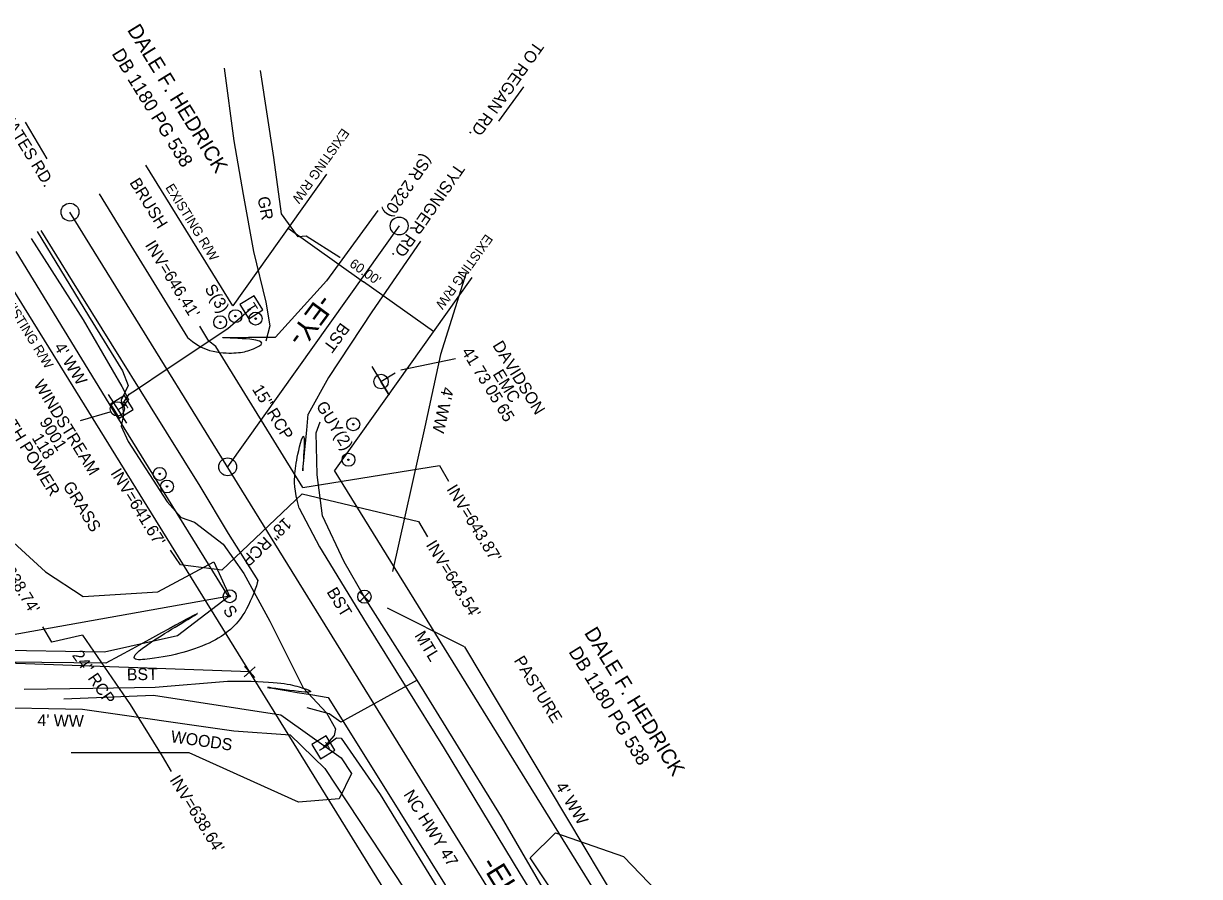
# Model space of a CAD drawing. Extents: x 1666477 to 1667385, y 697735 to 699095.
# Drawn here: x 1666778 to 1667173.7, y 698609.2 to 698896.5 of the extents above; entities that cross this region are included whole.
import ezdxf

# ---------------------------------------------------------------- set-up
doc = ezdxf.new("R2010")
doc.units = 0
for name, color, linetype in [('Exist Horizontal Alignment', 7, 'Continuous'), ('Exist Horizontal Alignment Direction Label', 7, 'Continuous'), ('Exist Horizontal Alignment Point', 7, 'Continuous'), ('Exist Other Culture Anchor (Guy Wire) CELL', 7, 'Continuous'), ('Exist Other Culture Fence Line', 7, 'Continuous'), ('Exist Other Culture Fence Line Text', 7, 'Continuous'), ('Exist Other Culture Gate', 7, 'Continuous'), ('Exist Other Culture Gate Text', 7, 'Continuous'), ('Exist Other Culture Sign CELL', 7, 'Continuous'), ('Exist Other Culture Sign Text', 7, 'Continuous'), ('Exist Property Corner CELL', 7, 'Continuous'), ('Exist Property Deed Book Text', 7, 'Continuous'), ('Exist Property Line', 7, 'Continuous'), ('Exist Property Owner Text', 7, 'Continuous'), ('Exist Right of Way Line', 7, 'Continuous'), ('Exist Right of Way Line Text', 7, 'Continuous'), ('Exist Right of Way Width CELL', 7, 'Continuous'), ('Exist Roads EOP', 7, 'Continuous'), ('Exist Roads EOP Leader', 7, 'Continuous'), ('Exist Roads EOP Text', 7, 'Continuous'), ('Exist Roads Soil', 7, 'Continuous'), ('Exist Roads Soil Text', 7, 'Continuous'), ('Exist Structure Minor Pipes RCP 15 Inch', 7, 'Continuous'), ('Exist Structure Minor Pipes RCP 15 Inch Invert', 7, 'Continuous'), ('Exist Structure Minor Pipes RCP 15 Inch Leader', 7, 'Continuous'), ('Exist Structure Minor Pipes RCP 15 Inch Text', 7, 'Continuous'), ('Exist Structure Minor Pipes RCP 18 Inch', 7, 'Continuous'), ('Exist Structure Minor Pipes RCP 18 Inch Invert', 7, 'Continuous'), ('Exist Structure Minor Pipes RCP 18 Inch Leader', 7, 'Continuous'), ('Exist Structure Minor Pipes RCP 18 Inch Text', 7, 'Continuous'), ('Exist Structure Minor Pipes RCP 24 Inch', 7, 'Continuous'), ('Exist Structure Minor Pipes RCP 24 Inch Invert', 7, 'Continuous'), ('Exist Structure Minor Pipes RCP 24 Inch Leader', 7, 'Continuous'), ('Exist Structure Minor Pipes RCP 24 Inch Text', 7, 'Continuous'), ('Exist Utilities Power Joint Use Telephone CELL', 7, 'Continuous'), ('Exist Utilities Power Joint Use Telephone Leader', 7, 'Continuous'), ('Exist Utilities Power Joint Use Telephone Text', 7, 'Continuous'), ('Exist Utilities Telephone Pedestal CELL', 7, 'Continuous'), ('Exist Utilities Telephone Pole CELL', 7, 'Continuous'), ('Exist Utilities Telephone Pole Leader', 7, 'Continuous'), ('Exist Utilities Telephone Pole Text', 7, 'Continuous'), ('Exist Utilities Telephone UG Cable SUE LOS C', 7, 'Continuous'), ('Exist Utilities Water UG Line SUE LOS C', 7, 'Continuous'), ('Exist Utilities Water Valve CELL', 7, 'Continuous'), ('Exist Vegetation Woods Line', 7, 'Continuous'), ('Exist Vegetation Woods Line Text', 7, 'Continuous')]:
    doc.layers.add(name, color=color, linetype=linetype)

msp = doc.modelspace()

# ---------------------------------------------------------------- linework, layer by layer
at = {"layer": 'Exist Horizontal Alignment'}
for p, q in [((1667148.23, 698259.58), (1666793.59, 698833.01)), ((1666904.4, 698828.35), (1666846.65, 698747.21))]:
    msp.add_line(p, q, dxfattribs=at)
at = {"layer": 'Exist Horizontal Alignment Point'}
for centre in [(1666793.59, 698833.01), (1666904.4, 698828.35), (1666846.66, 698747.21)]:
    msp.add_circle(centre, 3, dxfattribs=at)
at = {"layer": 'Exist Other Culture Anchor (Guy Wire) CELL'}
for centre, radius in [((1666888.93, 698761.56), 2.18), ((1666888.93, 698761.56), 0.24), ((1666887.33, 698749.59), 2.18), ((1666823.79, 698744.85), 2.18), ((1666887.33, 698749.59), 0.24), ((1666823.79, 698744.85), 0.24), ((1666826.25, 698740.6), 2.18), ((1666826.25, 698740.6), 0.24)]:
    msp.add_circle(centre, radius, dxfattribs=at)
at = {"layer": 'Exist Other Culture Fence Line'}
msp.add_line((1666926.39, 698686.64), (1666991.9, 698577.03), dxfattribs=at)
for points in [[(1666765.7, 698685.55), (1666805.24, 698684.86), (1666829.81, 698690.37), (1666846.99, 698703.56), (1666807.98, 698766.53), (1666775.47, 698819.74)], [(1666926.99, 698812.53), (1666918.33, 698785.01), (1666912.99, 698760.65), (1666902.09, 698711.93)], [(1666763.48, 698666.33), (1666797.8, 698665.64), (1666797.79, 698665.65), (1666848.77, 698658.33), (1666867.75, 698656.95), (1666879.42, 698645.59), (1666913.77, 698593.47), (1666938.8, 698553.46), (1666968.81, 698505.62), (1666992.27, 698464), (1667007.43, 698434.44)]]:
    msp.add_lwpolyline(points, dxfattribs=at)
at = {"layer": 'Exist Other Culture Gate'}
msp.add_line((1666926.39, 698686.64), (1666900.51, 698699.65), dxfattribs=at)
at = {"layer": 'Exist Other Culture Sign CELL'}
for centre, radius in [((1666849.29, 698797.97), 2.18), ((1666849.29, 698797.97), 0.24), ((1666856.08, 698797.14), 2.18), ((1666844.15, 698795.93), 2.18), ((1666844.15, 698795.93), 0.24), ((1666856.08, 698797.14), 0.24), ((1666847.36, 698703.64), 2.18), ((1666847.36, 698703.64), 0.24)]:
    msp.add_circle(centre, radius, dxfattribs=at)
at = {"layer": 'Exist Property Corner CELL'}
msp.add_line((1666854.1, 698678.14), (1666854.1, 698678.14), dxfattribs=at)
msp.add_lwpolyline([(1666855.93, 698679.84), (1666852.27, 698676.44), (1666854.1, 698678.14), (1666855.8, 698676.31), (1666852.39, 698679.97)], dxfattribs=at)
at = {"layer": 'Exist Property Line'}
msp.add_line((1666854.1, 698678.14), (1666599.41, 698687.39), dxfattribs=at)
at = {"layer": 'Exist Right of Way Line'}
for p, q in [((1666848.41, 698801.41), (1666819.1, 698848.79)), ((1666879.96, 698845.74), (1666848.41, 698801.41)), ((1667122.72, 698243.8), (1666768.07, 698817.23)), ((1666928.84, 698810.95), (1666882.65, 698746.04)), ((1667173.75, 698275.36), (1666882.65, 698746.04))]:
    msp.add_line(p, q, dxfattribs=at)
at = {"layer": 'Exist Right of Way Width CELL'}
for p in [(1666867.03, 698827.57), (1666915.91, 698792.78)]:
    msp.add_line(p, (1666892.41, 698809.51), dxfattribs=at)
at = {"layer": 'Exist Roads EOP'}
for points in [[(1666803.4, 698839.18), (1666814.05, 698821.74), (1666833.19, 698790.74)], [(1666897.2, 698833.52), (1666879.9, 698809.91), (1666862.77, 698790.89)], [(1666783.78, 698826.85), (1666794.34, 698809.8), (1666820.54, 698767.52), (1666837.34, 698740.76), (1666846.83, 698724.76), (1666856.77, 698708.99)], [(1666911.61, 698823.18), (1666895.16, 698799.38), (1666880.58, 698777.36), (1666873.81, 698765)], [(1666870.75, 698733.33), (1666877.61, 698720.31), (1666893.3, 698694.61), (1666919.49, 698652.35), (1666945, 698610.31), (1666971.56, 698567.04), (1666997.43, 698525.34), (1667023.64, 698482.78), (1667049.97, 698441.03), (1667054.17, 698434.34), (1667055.97, 698432.32), (1667056, 698431.95), (1667056.6, 698430.99)], [(1666805.65, 698681.07), (1666773.35, 698681.38)], [(1666778.16, 698672.37), (1666801.29, 698672.66), (1666822.31, 698673.06), (1666846.6, 698675.09)], [(1666880.47, 698669.55), (1666899.28, 698639.61), (1666924.98, 698598.12), (1666951.86, 698555.5), (1666977.68, 698512.7), (1667003.52, 698470.73), (1667029.64, 698428.31), (1667043.53, 698406.89), (1667043.73, 698406.63)]]:
    msp.add_lwpolyline(points, dxfattribs=at)
for points in [[(1666833.19, 698790.74), (1666837.58, 698786.86), (1666844.75, 698785.32), (1666851.46, 698785.64), (1666855.49, 698786.82), (1666862.77, 698790.89), (1666833.19, 698790.74), (1666862.77, 698790.89)], [(1666870.75, 698733.33), (1666869, 698739.55), (1666869.22, 698745.28), (1666870.12, 698751.47), (1666873.81, 698765), (1666870.75, 698733.33), (1666873.81, 698765)], [(1666856.77, 698708.99), (1666856.57, 698707.18), (1666852.74, 698697.92), (1666848.65, 698693.07), (1666842.23, 698688.26), (1666831.44, 698684.3), (1666821.38, 698682.47), (1666805.65, 698681.07), (1666856.77, 698708.99), (1666805.65, 698681.07)], [(1666846.6, 698675.09), (1666862.82, 698675.06), (1666871.25, 698673.31), (1666880.47, 698669.55), (1666846.6, 698675.09), (1666880.47, 698669.55)]]:
    msp.add_open_spline(points, degree=3, dxfattribs=at)
at = {"layer": 'Exist Roads EOP Leader'}
for points in [[(1666946.28, 698875.17), (1666937.78, 698863.66)], [(1666778.51, 698863.25), (1666785.83, 698850.96)]]:
    msp.add_lwpolyline(points, dxfattribs=at)
at = {"layer": 'Exist Roads Soil'}
for points in [[(1666845.46, 698881.53), (1666848.73, 698857.02), (1666851.83, 698838.9), (1666855.41, 698819.75), (1666859.46, 698802.71), (1666860.87, 698794.69), (1666859.47, 698789.51)], [(1666884.51, 698817.76), (1666884.47, 698817.75), (1666873.11, 698824.92), (1666870.45, 698824.72), (1666864.78, 698832.43), (1666862.19, 698851.45), (1666857.77, 698880.69)]]:
    msp.add_lwpolyline(points, dxfattribs=at)
at = {"layer": 'Exist Structure Minor Pipes RCP 15 Inch'}
msp.add_line((1666872.01, 698740.31), (1666842.63, 698787.74), dxfattribs=at)
at = {"layer": 'Exist Structure Minor Pipes RCP 15 Inch Leader'}
for points in [[(1666842.63, 698787.74), (1666840.32, 698789.5), (1666837.26, 698794.65)], [(1666872.01, 698740.31), (1666917.95, 698747.65), (1666920.94, 698742.45)]]:
    msp.add_lwpolyline(points, dxfattribs=at)
at = {"layer": 'Exist Structure Minor Pipes RCP 18 Inch'}
msp.add_line((1666871.77, 698738.09), (1666844.76, 698712.45), dxfattribs=at)
at = {"layer": 'Exist Structure Minor Pipes RCP 18 Inch Leader'}
for points in [[(1666871.77, 698738.09), (1666910.88, 698728.85), (1666913.94, 698723.69)], [(1666844.76, 698712.45), (1666830.83, 698714.21), (1666827.43, 698719.15)]]:
    msp.add_lwpolyline(points, dxfattribs=at)
at = {"layer": 'Exist Structure Minor Pipes RCP 24 Inch'}
msp.add_line((1666797.79, 698690.52), (1666813.8, 698667.16), dxfattribs=at)
at = {"layer": 'Exist Structure Minor Pipes RCP 24 Inch Leader'}
for points in [[(1666797.79, 698690.52), (1666787.5, 698688.2), (1666784.44, 698693.36)], [(1666813.8, 698667.16), (1666824.59, 698649.72), (1666827.68, 698644.58)]]:
    msp.add_lwpolyline(points, dxfattribs=at)
at = {"layer": 'Exist Utilities Power Joint Use Telephone CELL'}
msp.add_line((1666898.29, 698775.95), (1666898.29, 698775.95), dxfattribs=at)
msp.add_lwpolyline([(1666895.2, 698781.03), (1666901.06, 698771.32), (1666898.27, 698775.94), (1666903.09, 698778.87)], dxfattribs=at)
msp.add_circle((1666898.29, 698775.95), 2.45, dxfattribs=at)
at = {"layer": 'Exist Utilities Power Joint Use Telephone Leader'}
msp.add_line((1666904.91, 698779.87), (1666923.37, 698783.67), dxfattribs=at)
at = {"layer": 'Exist Utilities Telephone Pedestal CELL'}
for p, q in [((1666854.63, 698801.04), (1666854.63, 698801.04)), ((1666811.02, 698767.53), (1666811.02, 698767.53)), ((1666878.86, 698652.84), (1666878.86, 698652.84))]:
    msp.add_line(p, q, dxfattribs=at)
for points in [[(1666850.79, 698801.87), (1666853.74, 698797.12), (1666858.5, 698800.07), (1666855.55, 698804.82), (1666850.79, 698801.87)], [(1666807.18, 698768.35), (1666810.13, 698763.6), (1666814.88, 698766.55), (1666811.93, 698771.3), (1666807.18, 698768.35)], [(1666875.03, 698653.68), (1666877.96, 698648.91), (1666882.73, 698651.85), (1666879.79, 698656.61), (1666875.03, 698653.68)]]:
    msp.add_lwpolyline(points, dxfattribs=at)
at = {"layer": 'Exist Utilities Telephone Pole CELL'}
for p, q in [((1666806.5, 698771.53), (1666812.6, 698761.98)), ((1666809.55, 698766.75), (1666809.55, 698766.75))]:
    msp.add_line(p, q, dxfattribs=at)
msp.add_circle((1666809.55, 698766.75), 2.41, dxfattribs=at)
at = {"layer": 'Exist Utilities Telephone Pole Leader'}
msp.add_line((1666807.05, 698765.63), (1666797.06, 698762.66), dxfattribs=at)
at = {"layer": 'Exist Utilities Telephone UG Cable SUE LOS C'}
for points in [[(1666782.53, 698826.44), (1666799.81, 698798.03), (1666811.32, 698779.59), (1666813.23, 698774.6), (1666810.77, 698769.62), (1666811.38, 698766.84), (1666811.63, 698764.7), (1666810.81, 698760.95), (1666813.15, 698755.81), (1666826.32, 698735.48), (1666831.02, 698730.12), (1666835.56, 698728.55), (1666845.16, 698721.16), (1666852.11, 698711.31), (1666860.89, 698695.27), (1666872.06, 698672.78), (1666879.9, 698664.39), (1666882.94, 698659), (1666882.55, 698656.73), (1666880.09, 698653.9), (1666881.02, 698654.39), (1666878.94, 698652.93)], [(1666780.57, 698824.13), (1666798.05, 698796.74), (1666811.03, 698774.3), (1666813.24, 698769.92), (1666811.46, 698767.78)], [(1666811.01, 698768.02), (1666813.55, 698771.71), (1666815.99, 698773.31), (1666826.01, 698779.96), (1666846.68, 698793.81), (1666854.51, 698800.55)], [(1666879.11, 698652.82), (1666883.33, 698655.98), (1666884.9, 698655.82), (1666898.04, 698636.86), (1666923.51, 698595.3), (1666949.94, 698553.7), (1666963.27, 698526.7), (1666963.8, 698522.77), (1666984.35, 698489.78), (1666990.94, 698476.64), (1667004.92, 698449.71), (1667010.1, 698440.1), (1667007, 698437.59)]]:
    msp.add_lwpolyline(points, dxfattribs=at)
at = {"layer": 'Exist Utilities Water UG Line SUE LOS C'}
for points in [[(1666876.74, 698744.58), (1666876.47, 698758.66), (1666877.77, 698762.39)], [(1666910.42, 698675.41), (1666892.7, 698703.36), (1666885.87, 698715.18), (1666878.61, 698730.69), (1666876.74, 698744.58)], [(1667059.41, 698444.14), (1667051.92, 698448.86), (1667045.14, 698458.4), (1667032.4, 698476.75), (1667019.73, 698495.63), (1666997.89, 698531.42), (1666986.24, 698552.11), (1666969.96, 698576.95), (1666955.37, 698600.92), (1666938.85, 698629.31), (1666923.47, 698654.27), (1666910.42, 698675.41), (1666884.79, 698661.27), (1666880.83, 698664.06), (1666873.43, 698666)]]:
    msp.add_lwpolyline(points, dxfattribs=at)
at = {"layer": 'Exist Utilities Water Valve CELL'}
msp.add_lwpolyline([(1666894.27, 698705.06), (1666891.11, 698701.91), (1666892.69, 698703.49), (1666894.27, 698701.91), (1666891.11, 698705.06)], dxfattribs=at)
msp.add_circle((1666892.69, 698703.49), 2.23, dxfattribs=at)
at = {"layer": 'Exist Vegetation Woods Line'}
for points in [[(1666767.69, 698727.95), (1666785.4, 698711.88), (1666798.08, 698703.59), (1666823.22, 698705.08), (1666842, 698715.28), (1666847.33, 698703.65), (1666770.13, 698689.87)], [(1666791.52, 698669.07), (1666821.73, 698670.35), (1666864.58, 698663.64), (1666884.87, 698649.22), (1666888.32, 698643.89)], [(1666888.32, 698643.89), (1666884.15, 698635.36), (1666870.48, 698634.32), (1666833.7, 698650.92), (1666794.02, 698650.95)], [(1666997.11, 698574.49), (1666965.25, 698590.45), (1666948.43, 698615.52), (1666956.99, 698623.99), (1666979.86, 698615.98), (1667005.31, 698589.51), (1667026.65, 698580.74), (1667046.61, 698594.4)]]:
    msp.add_lwpolyline(points, dxfattribs=at)

# ---------------------------------------------------------------- texts
at = {"layer": 'Exist Horizontal Alignment Direction Label'}
for s, rotation, p in [('-EY-', 233.487, (1666877.68, 698805.9)), ('-EL-', 301.6959, (1666931.68, 698613.44))]:
    msp.add_text(s, height=7, rotation=rotation, dxfattribs=at).set_placement(p)
at = {"layer": 'Exist Other Culture Fence Line Text'}
for rotation, p in [(301.4175, (1666788.08, 698787.59)), (257.2589, (1666918.93, 698774.38)), (358.8481, (1666782.62, 698659.94)), (300.8653, (1666956.82, 698639.62))]:
    msp.add_text("4' WW", height=4, rotation=rotation, dxfattribs=at).set_placement(p)
at = {"layer": 'Exist Other Culture Gate Text'}
msp.add_text('MTL', height=4, rotation=301.3048, dxfattribs=at).set_placement((1666909.42, 698690.43))
at = {"layer": 'Exist Other Culture Sign Text'}
for s, rotation, p in [('S(3)', 301.6959, (1666838.77, 698807.22)), ('GUY(2)', 301.6959, (1666876.25, 698767.8)), ('S', 305.0453, (1666844.92, 698698.86))]:
    msp.add_text(s, height=4, rotation=rotation, dxfattribs=at).set_placement(p)
at = {"layer": 'Exist Property Deed Book Text'}
for p in [(1666807.5, 698886.38), (1666961.26, 698684.94)]:
    msp.add_text('DB 1180 PG 538', height=4.5, rotation=301.6959, dxfattribs=at).set_placement(p)
at = {"layer": 'Exist Property Owner Text'}
for p in [(1666812.71, 698894.38), (1666966.52, 698691.31)]:
    msp.add_text('DALE F. HEDRICK', height=5, rotation=301.6959, dxfattribs=at).set_placement(p)
at = {"layer": 'Exist Right of Way Line Text'}
for rotation, p in [(234.5614, (1666885.27, 698861.48)), (301.7353, (1666825.6, 698841.33)), (234.5614, (1666933.54, 698825.83)), (301.7353, (1666769.97, 698805.03))]:
    msp.add_text('EXISTING R/W', height=3.2, rotation=rotation, dxfattribs=at).set_placement(p)
at = {"layer": 'Exist Right of Way Width CELL'}
msp.add_text("60.00'", height=3.2, rotation=324.5614, dxfattribs=at).set_placement((1666887.4, 698814.94))
at = {"layer": 'Exist Roads EOP Text'}
for s, rotation, p in [('TO REGAN RD.', 234.5922, (1666950.04, 698890.87)), ('TO YATES RD.', 301.7909, (1666765.62, 698872.62)), ('(SR 2320)', 235.209, (1666912.6, 698852.93)), ('TYSINGER RD.', 235.209, (1666923.41, 698849.74)), ('BST', 233.7808, (1666884.78, 698796.06)), ('BST', 301.4037, (1666879.85, 698705.12)), ('BST', 1.112, (1666812.77, 698675.29)), ('NC HWY 47', 301.8986, (1666905.7, 698636.88))]:
    msp.add_text(s, height=4, rotation=rotation, dxfattribs=at).set_placement(p)
at = {"layer": 'Exist Roads Soil Text'}
msp.add_text('GR', height=4, rotation=280.5719, dxfattribs=at).set_placement((1666856.7, 698837.91))
at = {"layer": 'Exist Structure Minor Pipes RCP 15 Inch Invert'}
for s, p in [("INV=646.41'", (1666818.71, 698821.94)), ("INV=643.87'", (1666920.2, 698739.72))]:
    msp.add_text(s, height=4, rotation=301.6959, dxfattribs=at).set_placement(p)
at = {"layer": 'Exist Structure Minor Pipes RCP 15 Inch Text'}
msp.add_text('15" RCP', height=4, rotation=301.7853, dxfattribs=at).set_placement((1666854.74, 698773.4))
at = {"layer": 'Exist Structure Minor Pipes RCP 18 Inch Invert'}
for s, p in [("INV=641.67'", (1666807.12, 698745.14)), ("INV=643.54'", (1666913.25, 698720.95))]:
    msp.add_text(s, height=4, rotation=301.6959, dxfattribs=at).set_placement(p)
at = {"layer": 'Exist Structure Minor Pipes RCP 18 Inch Text'}
msp.add_text('18" RCP', height=4, rotation=223.4985, dxfattribs=at).set_placement((1666865.9, 698730.44))
at = {"layer": 'Exist Structure Minor Pipes RCP 24 Inch Invert'}
for s, p in [("INV=638.74'", (1666764.84, 698722.43)), ("INV=638.64'", (1666827, 698641.84))]:
    msp.add_text(s, height=4, rotation=301.6959, dxfattribs=at).set_placement(p)
at = {"layer": 'Exist Structure Minor Pipes RCP 24 Inch Text'}
msp.add_text('24" RCP', height=4, rotation=304.443, dxfattribs=at).set_placement((1666794.15, 698683.75))
at = {"layer": 'Exist Utilities Power Joint Use Telephone Text'}
for s, p in [('41 73 05 65', (1666925.23, 698785.99)), ('DAVIDSON', (1666935.68, 698788.14)), ('EMC', (1666935.75, 698778.49))]:
    msp.add_text(s, height=4, rotation=301.6959, dxfattribs=at).set_placement(p)
at = {"layer": 'Exist Utilities Telephone Pedestal CELL'}
for rotation, p in [(301.8292, (1666852.58, 698801.1)), (301.8292, (1666808.96, 698767.59)), (301.6399, (1666876.81, 698652.9))]:
    msp.add_text('T', height=3.42, rotation=rotation, dxfattribs=at).set_placement(p)
at = {"layer": 'Exist Utilities Telephone Pole Text'}
for s, p in [('WINDSTREAM', (1666781.21, 698775.05)), ('WITH POWER', (1666768.53, 698767)), ('9001', (1666783.17, 698762.35)), ('118', (1666780.62, 698756.96))]:
    msp.add_text(s, height=4, rotation=301.6959, dxfattribs=at).set_placement(p)
at = {"layer": 'Exist Vegetation Woods Line Text'}
for s, rotation, p in [('BRUSH', 301.6959, (1666813.49, 698842.97)), ('GRASS', 301.6959, (1666791.05, 698740.8)), ('PASTURE', 301.6959, (1666942.87, 698682.03)), ('WOODS', 352.0253, (1666827.34, 698654.5))]:
    msp.add_text(s, height=4, rotation=rotation, dxfattribs=at).set_placement(p)

doc.saveas('drawing.dxf')
